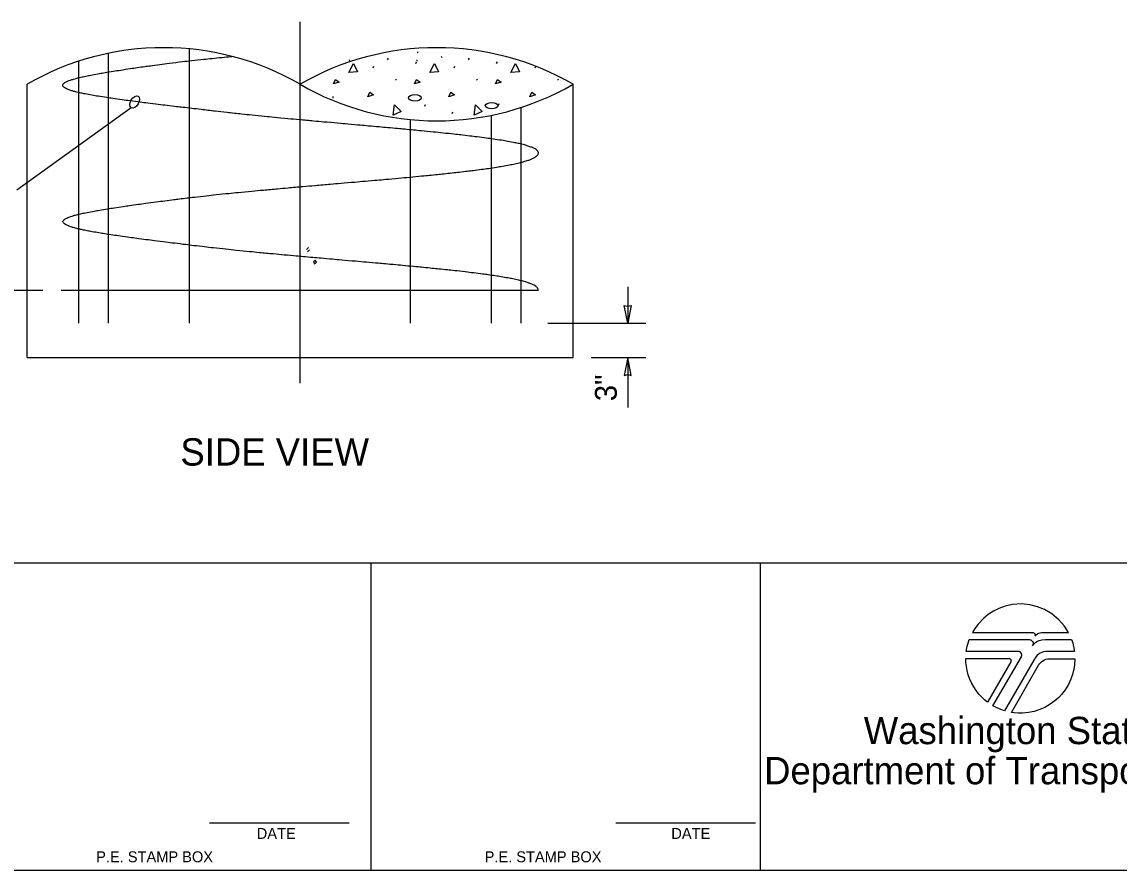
# Model space of a CAD drawing. Extents: x 99862 to 104211, y 98939 to 105076.
# Drawn here: x 101519 to 102323, y 100000 to 100621 of the extents above; entities that cross this region are included whole.
import ezdxf

# ---------------------------------------------------------------- set-up
doc = ezdxf.new("R2010")
doc.units = 0
for name, color, linetype in [('Level 10', 7, 'Continuous'), ('Level 11', 7, 'Continuous'), ('Level 12', 7, 'Continuous'), ('Level 15', 7, 'Continuous'), ('Level 2', 7, 'Continuous'), ('Level 20', 7, 'Continuous'), ('Level 60', 7, 'Continuous')]:
    doc.layers.add(name, color=color, linetype=linetype)

msp = doc.modelspace()

# ---------------------------------------------------------------- linework, layer by layer
at = {"layer": 'Level 10'}
for p, q in [((101582.89, 100400.28), (101582.89, 100597.98)), ((101642.17, 100400.28), (101642.17, 100601.17)), ((101561.19, 100400.28), (101561.19, 100592.23)), ((101759.13, 100593.24), (101759.24, 100592.25)), ((101808.57, 100593.24), (101808.68, 100592.25)), ((101723.16, 100484.84), (101723.16, 100575.28)), ((101868.41, 100560.11), (101868.93, 100561.28)), ((101885.12, 100400.28), (101885.12, 100558.32)), ((101804.14, 100400.28), (101804.14, 100549.39)), ((101863.42, 100400.28), (101863.42, 100552.58)), ((101723.16, 100400.28), (101723.16, 100474.91)), ((101897.51, 100424.35), (101548.15, 100424.35))]:
    msp.add_line(p, q, dxfattribs=at)
for centre in [(101807.27, 100565.35), (101863.49, 100559.63)]:
    msp.add_ellipse(centre, major_axis=(4.7, 0), ratio=0.5, dxfattribs=at)
msp.add_open_spline([(101897.51, 100424.35), (101897.52, 100425.61), (101897.02, 100426.41), (101895.26, 100427.81), (101894.16, 100428.41), (101891.55, 100429.51), (101890.12, 100430.01), (101886.31, 100431.14), (101883.79, 100431.77), (101878.52, 100432.89), (101875.91, 100433.39), (101869.96, 100434.42), (101866.59, 100434.95), (101860.35, 100435.85), (101857.61, 100436.22), (101849.87, 100437.23), (101844.67, 100437.85), (101835.5, 100438.88), (101831.73, 100439.29), (101824.21, 100440.07), (101820.5, 100440.45), (101812.88, 100441.2), (101808.97, 100441.57), (101799.44, 100442.47), (101793.76, 100443), (101784.67, 100443.81), (101781.37, 100444.11), (101771.35, 100444.99), (101764.57, 100445.59), (101752.69, 100446.63), (101747.65, 100447.07), (101737.86, 100447.93), (101733.12, 100448.35), (101724.84, 100449.08), (101721.32, 100449.4), (101711.02, 100450.33), (101704.29, 100450.95), (101692.38, 100452.08), (101687.22, 100452.58), (101675.8, 100453.72), (101669.61, 100454.37), (101658.72, 100455.55), (101653.99, 100456.09), (101644.69, 100457.2), (101640.13, 100457.75), (101630.52, 100458.96), (101625.53, 100459.58), (101615.8, 100460.81), (101611.09, 100461.42), (101602.73, 100462.52), (101599.04, 100463.02), (101590.9, 100464.15), (101586.6, 100464.77), (101579.33, 100465.9), (101576.27, 100466.4), (101570.36, 100467.42), (101567.56, 100467.95), (101563.24, 100468.86), (101561.58, 100469.23), (101557.53, 100470.23), (101555.43, 100470.86), (101552.72, 100471.89), (101551.84, 100472.3), (101550.55, 100473.08), (101550.1, 100473.46), (101549.48, 100474.3), (101549.41, 100474.77), (101549.78, 100475.61), (101550.12, 100475.99), (101551.24, 100476.81), (101552.08, 100477.26), (101553.99, 100478.05), (101554.95, 100478.39), (101557.4, 100479.16), (101558.93, 100479.58), (101563.41, 100480.68), (101566.62, 100481.36), (101572.93, 100482.55), (101575.78, 100483.06), (101582.54, 100484.18), (101586.53, 100484.8), (101594.15, 100485.93), (101597.64, 100486.43), (101605.19, 100487.49), (101609.26, 100488.05), (101618.44, 100489.29), (101623.59, 100489.97), (101631.46, 100491), (101634.02, 100491.32), (101640.77, 100492.15), (101645.03, 100492.65), (101655.09, 100493.78), (101660.95, 100494.41), (101671.88, 100495.53), (101676.9, 100496.03), (101688.62, 100497.16), (101695.32, 100497.78), (101707.66, 100498.9), (101713.25, 100499.4), (101726.09, 100500.53), (101733.29, 100501.16), (101746.34, 100502.28), (101752.15, 100502.78), (101764.13, 100503.81), (101770.25, 100504.34), (101780.57, 100505.24), (101784.81, 100505.62), (101795.98, 100506.62), (101802.75, 100507.25), (101813.31, 100508.25), (101817.21, 100508.64), (101824.43, 100509.36), (101827.75, 100509.71), (101835.2, 100510.51), (101839.26, 100510.96), (101846.34, 100511.79), (101849.41, 100512.17), (101856.68, 100513.1), (101860.72, 100513.66), (101867.77, 100514.72), (101870.84, 100515.22), (101877.1, 100516.34), (101880.16, 100516.96), (101884.99, 100518.09), (101886.88, 100518.6), (101890.54, 100519.72), (101892.21, 100520.34), (101894.6, 100521.47), (101895.44, 100521.98), (101896.51, 100522.82), (101896.84, 100523.15), (101897.36, 100523.83), (101897.54, 100524.17), (101897.78, 100525.05), (101897.7, 100525.58), (101897.02, 100526.76), (101896.27, 100527.4), (101894.27, 100528.53), (101893.14, 100529.03), (101890.01, 100530.16), (101887.85, 100530.79), (101883.22, 100531.91), (101880.89, 100532.41), (101874.98, 100533.54), (101871.27, 100534.16), (101863.84, 100535.29), (101860.27, 100535.79), (101852.36, 100536.81), (101848.01, 100537.35), (101840.14, 100538.25), (101836.75, 100538.63), (101827.39, 100539.63), (101821.25, 100540.25), (101810.92, 100541.26), (101806.92, 100541.64), (101799.17, 100542.37), (101795.45, 100542.72), (101786.75, 100543.51), (101781.74, 100543.97), (101772.48, 100544.8), (101768.26, 100545.17), (101757.78, 100546.1), (101751.5, 100546.66), (101739.61, 100547.73), (101734.04, 100548.23), (101721.75, 100549.35), (101715.05, 100549.97), (101703.19, 100551.1), (101698.02, 100551.6), (101687.12, 100552.69), (101681.41, 100553.28), (101668.67, 100554.65), (101661.73, 100555.44), (101649.54, 100556.89), (101644.26, 100557.51), (101636.3, 100558.46), (101633.54, 100558.78), (101625.28, 100559.76), (101619.97, 100560.41), (101610.73, 100561.54), (101606.76, 100562.04), (101597.98, 100563.17), (101593.31, 100563.8), (101585.35, 100564.92), (101581.98, 100565.42), (101574.79, 100566.54), (101571.14, 100567.17), (101565.22, 100568.29), (101562.84, 100568.79), (101558.47, 100569.82), (101556.54, 100570.35), (101553.8, 100571.26), (101552.83, 100571.63), (101551.24, 100572.38), (101550.62, 100572.76), (101549.55, 100573.66), (101549.26, 100574.18), (101549.35, 100575), (101549.49, 100575.29), (101550.22, 100576.18), (101551.14, 100576.78), (101553.43, 100577.81), (101554.62, 100578.25), (101557.34, 100579.11), (101558.84, 100579.53), (101561.77, 100580.27), (101563.11, 100580.58), (101567.34, 100581.51), (101570.48, 100582.14), (101576.68, 100583.26), (101579.6, 100583.77), (101586.74, 100584.94), (101591.07, 100585.62), (101599.51, 100586.88), (101603.49, 100587.47), (101610.14, 100588.42), (101612.69, 100588.78), (101620.82, 100589.91), (101626.59, 100590.66), (101637.79, 100592), (101643.12, 100592.6), (101653.29, 100593.7), (101658.08, 100594.2), (101666.35, 100595.03), (101669.77, 100595.37), (101673.22, 100595.7)], degree=3, dxfattribs=at)
at = {"layer": 'Level 11'}
for p, q in [((101727.81, 100454.26), (101729.27, 100455.72)), ((101728.59, 100452.68), (101730.02, 100454.11)), ((101734.23, 100446.54), (101732.94, 100445.24)), ((101733.88, 100443.84), (101735.16, 100445.11))]:
    msp.add_line(p, q, dxfattribs=at)
for points in [[(101734.24, 100446.54), (101734.23, 100446.54)], [(101735.16, 100445.11), (101735.16, 100445.11)]]:
    msp.add_lwpolyline(points, dxfattribs=at)
for points in [[(101732.94, 100445.24), (101733.4, 100444.54), (101733.88, 100443.84)], [(101735.16, 100445.11), (101734.69, 100445.83), (101734.24, 100446.54)]]:
    msp.add_open_spline(points, degree=2, dxfattribs=at)
at = {"layer": 'Level 12'}
for p, q in [((101808.83, 100599.14), (101809.36, 100598.35)), ((101826.57, 100595.78), (101827.1, 100595)), ((101776.62, 100587.43), (101777.14, 100588.61)), ((101787.29, 100593.21), (101787.82, 100594.39)), ((101807.83, 100590.46), (101808.36, 100591.64)), ((101835.95, 100587.43), (101836.47, 100588.61)), ((101846.61, 100593.21), (101847.14, 100594.39)), ((101867.16, 100590.46), (101867.69, 100591.64)), ((101895.28, 100587.43), (101895.8, 100588.61)), ((101793.08, 100579), (101793.61, 100578.21)), ((101852.41, 100579), (101852.94, 100578.21)), ((101911.74, 100579), (101912.26, 100578.21)), ((101747.07, 100566.37), (101747.2, 100565.18)), ((101814.61, 100559.37), (101815.14, 100560.56)), ((101834.63, 100553.98), (101835.16, 100555.16))]:
    msp.add_line(p, q, dxfattribs=at)
for points in [[(101758.84, 100583.88), (101762.39, 100590.59), (101765.16, 100584.4), (101758.97, 100583.88)], [(101818.17, 100583.88), (101821.72, 100590.59), (101824.49, 100584.4), (101818.3, 100583.88)], [(101877.49, 100583.88), (101881.05, 100590.59), (101883.82, 100584.4), (101877.63, 100583.88)], [(101747.59, 100575.58), (101749.16, 100578.87), (101751.8, 100576.89), (101747.59, 100575.58)], [(101806.91, 100575.58), (101808.49, 100578.87), (101811.13, 100576.89), (101806.91, 100575.58)], [(101866.24, 100575.58), (101867.82, 100578.87), (101870.45, 100576.89), (101866.24, 100575.58)], [(101772.7, 100566.16), (101774.28, 100569.45), (101776.91, 100567.48), (101772.7, 100566.16)], [(101832.02, 100566.16), (101833.6, 100569.45), (101836.24, 100567.48), (101832.02, 100566.16)], [(101891.35, 100566.16), (101892.93, 100569.45), (101895.56, 100567.48), (101891.35, 100566.16)], [(101791.32, 100552.62), (101792.37, 100560.14), (101797.09, 100555.27), (101791.45, 100552.66)], [(101850.65, 100552.62), (101851.7, 100560.14), (101856.42, 100555.27), (101850.78, 100552.66)]]:
    msp.add_lwpolyline(points, dxfattribs=at)
at = {"layer": 'Level 15'}
for p, q in [((101723.16, 100356.35), (101723.16, 100620.91)), ((101599.5, 100558.01), (101515.67, 100497.85)), ((101963.16, 100426.94), (101963.16, 100400.28)), ((101534.81, 100424.35), (101396.49, 100424.35)), ((101904.71, 100400.28), (101976.49, 100400.28)), ((101936.49, 100375.28), (101976.49, 100375.28)), ((101963.16, 100375.28), (101963.16, 100338.54))]:
    msp.add_line(p, q, dxfattribs=at)
for points in [[(101963.16, 100400.28), (101960.59, 100413.38), (101963.16, 100412.77), (101965.73, 100413.38)], [(101963.16, 100375.28), (101960.59, 100362.17), (101963.16, 100362.78), (101965.73, 100362.17)]]:
    msp.add_lwpolyline(points, close=True, dxfattribs=at)
msp.add_ellipse((101602, 100562.34), major_axis=(-2.5, -4.33), ratio=0.57735, dxfattribs=at)
at = {"layer": 'Level 2'}
for p, q in [((101523.16, 100375.28), (101523.16, 100575.28)), ((101923.16, 100375.28), (101923.16, 100575.28)), ((101523.16, 100375.28), (101523.16, 100375.28)), ((101523.16, 100375.28), (101923.16, 100375.28)), ((101923.16, 100375.28), (101923.16, 100375.28))]:
    msp.add_line(p, q, dxfattribs=at)
for centre, start, end in [((101623.16, 100402.07), 60, 120), ((101823.16, 100402.07), 60, 120), ((101823.16, 100748.48), 240, 300)]:
    msp.add_arc(centre, 200, start, end, dxfattribs=at)
at = {"layer": 'Level 60'}
for p, q in [((100000, 100225), (103150, 100225)), ((101775.14, 100000), (101775.14, 100225)), ((102060.14, 100225), (102060.14, 100000)), ((101656.73, 100034.63), (101759, 100034.63)), ((101954.38, 100034.63), (102056.64, 100034.63)), ((100000, 100000), (103150, 100000))]:
    msp.add_line(p, q, dxfattribs=at)
for points in [[(102215.65, 100173.9), (102259.93, 100173.9), (102260.72, 100173.72), (102261.37, 100173.19), (102261.67, 100172.58), (102261.73, 100172.01), (102261.49, 100171.19), (102262.28, 100172.2), (102263.47, 100173.12), (102265.22, 100173.79), (102266.37, 100173.9), (102285.93, 100173.91), (102283.01, 100178.5), (102278.88, 100183.29), (102273.75, 100187.57), (102268.34, 100190.76), (102263.32, 100192.81), (102257.62, 100194.23), (102251.64, 100194.81), (102245.06, 100194.41), (102239.72, 100193.26), (102235.06, 100191.6), (102231.09, 100189.63), (102227.31, 100187.2), (102223.74, 100184.28), (102219.78, 100180.08), (102217.47, 100176.94)], [(102215.65, 100173.9), (102259.93, 100173.9), (102260.72, 100173.72), (102261.37, 100173.19), (102261.67, 100172.58), (102261.73, 100172.01), (102261.49, 100171.19), (102262.28, 100172.2), (102263.47, 100173.12), (102265.22, 100173.79), (102266.37, 100173.9), (102285.93, 100173.91), (102283.01, 100178.5), (102278.88, 100183.29), (102273.75, 100187.57), (102268.34, 100190.76), (102263.32, 100192.81), (102257.62, 100194.23), (102251.64, 100194.81), (102245.06, 100194.41), (102239.72, 100193.26), (102235.06, 100191.6), (102231.09, 100189.63), (102227.31, 100187.2), (102223.74, 100184.28), (102219.78, 100180.08), (102217.47, 100176.94)], [(102213.29, 100168.72), (102257.21, 100168.71), (102257.88, 100168.64), (102258.46, 100168.44), (102258.93, 100168.16), (102259.22, 100167.93), (102259.69, 100167.35), (102260.04, 100166.62), (102260.18, 100165.95), (102260.12, 100165.22), (102259.97, 100164.68), (102259.72, 100164.19), (102260.25, 100164.92), (102261.1, 100165.91), (102262.11, 100166.78), (102263.44, 100167.62), (102264.65, 100168.15), (102266.49, 100168.61), (102269.17, 100168.71), (102288.29, 100168.71), (102289.11, 100166.24), (102289.58, 100164.53), (102289.98, 100162.72), (102290.31, 100160.88), (102290.43, 100160.06), (102272.02, 100160.06), (102269.5, 100160.01), (102267.71, 100159.7), (102265.21, 100158.68), (102263.18, 100157.22), (102261.82, 100155.71), (102260.6, 100153.75), (102239.14, 100116.61), (102236.5, 100117.51), (102234.2, 100118.47), (102232.2, 100119.45), (102230.68, 100120.29), (102251.54, 100156.11), (102251.93, 100157.41), (102251.64, 100158.57), (102250.69, 100159.64), (102249.9, 100159.98), (102249.27, 100160.06), (102211.15, 100160.06), (102211.57, 100162.58), (102211.83, 100163.87), (102212.19, 100165.26), (102212.72, 100167.04)], [(102210.8, 100154.85), (102242.31, 100154.84), (102242.71, 100154.79), (102243.19, 100154.59), (102243.46, 100154.37), (102243.71, 100154.07), (102243.86, 100153.74), (102243.95, 100153.34), (102243.92, 100152.86), (102243.73, 100152.37), (102226.65, 100122.98), (102224.53, 100124.7), (102222.55, 100126.55), (102220.7, 100128.52), (102218.31, 100131.53), (102216.6, 100134.12), (102215, 100137.03), (102213.59, 100140.19), (102212.6, 100143.04), (102211.8, 100146), (102211.24, 100149.02), (102210.92, 100151.96)], [(102244.22, 100115.41), (102264.18, 100149.96), (102264.77, 100150.86), (102265.42, 100151.65), (102266.29, 100152.48), (102267.18, 100153.15), (102268.34, 100153.8), (102269.51, 100154.27), (102270.8, 100154.58), (102271.5, 100154.68), (102272.42, 100154.72), (102290.77, 100154.71), (102290.51, 100150.33), (102289.96, 100146.87), (102288.82, 100142.52), (102287.62, 100139.29), (102285.98, 100135.88), (102283.5, 100131.87), (102280.8, 100128.43), (102278.86, 100126.38), (102276.15, 100123.94), (102272.71, 100121.41), (102268.67, 100119.09), (102265.01, 100117.48), (102260.85, 100116.15), (102256.85, 100115.33), (102252.39, 100114.9), (102249.21, 100114.9), (102246.3, 100115.12)]]:
    msp.add_lwpolyline(points, close=True, dxfattribs=at)

# ---------------------------------------------------------------- texts
at = {"layer": 'Level 20'}
msp.add_text('3"', height=16, rotation=90, dxfattribs=at).set_placement((101955.16, 100343.28))
msp.add_text('SIDE VIEW', height=20, dxfattribs=at).set_placement((101635.47, 100296.13))
at = {"layer": 'Level 60'}
for s, height, p in [('Washington State', 19.999, (102136.05, 100092.17)), ('Department of Transportation', 19.999, (102063.07, 100062.8)), ('DATE', 8.032, (101691.37, 100022.78)), ('DATE', 8.032, (101995.07, 100022.78)), ('P.E. STAMP BOX', 8, (101573.79, 100005.71)), ('P.E. STAMP BOX', 8, (101858.35, 100005.71))]:
    msp.add_text(s, height=height, dxfattribs=at).set_placement(p)

doc.saveas('drawing.dxf')
